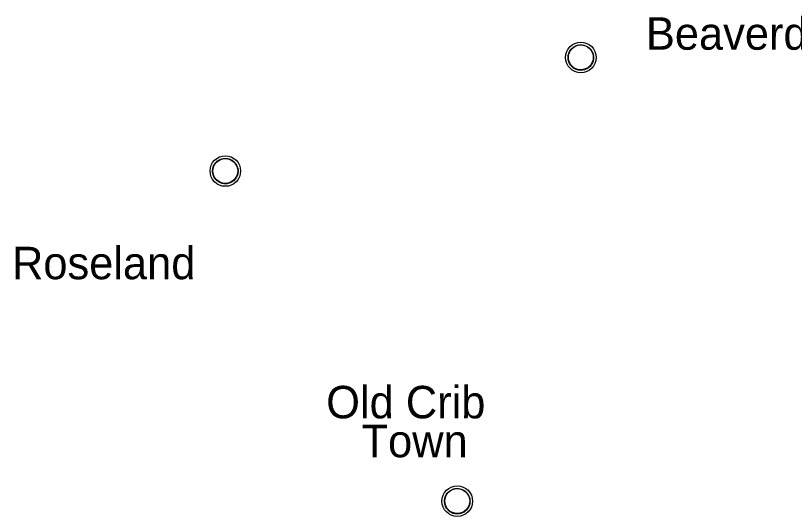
# Model space of a CAD drawing. Extents: x 5197761 to 5514561, y 1890130 to 2080942.
# Drawn here: x 5278705 to 5297901, y 1968768 to 1981120 of the extents above; entities that cross this region are included whole.
import ezdxf

# ---------------------------------------------------------------- set-up
doc = ezdxf.new("R2010")
doc.units = 0
doc.layers.add('Exist Civil Demographics Community CELL', color=7, linetype='Continuous')
doc.layers.add('Exist Civil Demographics Community Label', color=7, linetype='Continuous')

msp = doc.modelspace()

# ---------------------------------------------------------------- linework, layer by layer
at = {"layer": 'Exist Civil Demographics Community CELL'}
for points in [[(5292327, 1980137), (5292331, 1980159), (5292338, 1980185), (5292350, 1980214), (5292361, 1980237), (5292375, 1980260), (5292390, 1980280), (5292406, 1980298), (5292424, 1980316), (5292446, 1980335), (5292468, 1980349), (5292487, 1980361), (5292508, 1980371), (5292529, 1980380), (5292552, 1980387), (5292569, 1980392), (5292589, 1980395), (5292605, 1980398), (5292631, 1980399), (5292648, 1980398), (5292671, 1980397), (5292691, 1980394), (5292710, 1980390), (5292730, 1980385), (5292751, 1980377), (5292777, 1980365), (5292803, 1980351), (5292823, 1980337), (5292843, 1980321), (5292857, 1980308), (5292873, 1980291), (5292889, 1980272), (5292901, 1980254), (5292913, 1980234), (5292923, 1980213), (5292931, 1980193), (5292938, 1980173), (5292943, 1980155), (5292947, 1980130), (5292950, 1980112), (5292951, 1980088), (5292950, 1980064), (5292948, 1980042), (5292944, 1980020), (5292937, 1979995), (5292930, 1979972), (5292921, 1979951), (5292908, 1979927), (5292895, 1979906), (5292881, 1979887), (5292864, 1979868), (5292843, 1979849), (5292823, 1979832), (5292803, 1979818), (5292786, 1979808), (5292758, 1979795), (5292730, 1979785), (5292706, 1979779), (5292680, 1979773), (5292662, 1979772), (5292644, 1979771), (5292622, 1979771), (5292604, 1979772), (5292582, 1979775), (5292558, 1979780), (5292540, 1979786), (5292519, 1979793), (5292501, 1979801), (5292485, 1979810), (5292458, 1979826), (5292436, 1979843), (5292416, 1979861), (5292398, 1979881), (5292385, 1979897), (5292374, 1979913), (5292357, 1979942), (5292350, 1979956), (5292343, 1979972), (5292333, 1980005), (5292327, 1980033), (5292324, 1980054), (5292323, 1980079), (5292323, 1980098), (5292325, 1980123)], [(5283565, 1977336), (5283569, 1977358), (5283576, 1977385), (5283587, 1977414), (5283599, 1977436), (5283612, 1977459), (5283628, 1977480), (5283643, 1977497), (5283662, 1977516), (5283684, 1977534), (5283706, 1977549), (5283725, 1977560), (5283745, 1977570), (5283767, 1977579), (5283790, 1977587), (5283807, 1977591), (5283826, 1977594), (5283843, 1977597), (5283868, 1977598), (5283886, 1977598), (5283909, 1977597), (5283928, 1977594), (5283948, 1977590), (5283968, 1977584), (5283989, 1977576), (5284015, 1977565), (5284040, 1977551), (5284061, 1977536), (5284081, 1977520), (5284095, 1977508), (5284111, 1977490), (5284126, 1977472), (5284139, 1977453), (5284151, 1977433), (5284161, 1977412), (5284169, 1977392), (5284175, 1977372), (5284181, 1977354), (5284185, 1977330), (5284187, 1977311), (5284189, 1977287), (5284188, 1977264), (5284186, 1977241), (5284182, 1977219), (5284175, 1977195), (5284168, 1977171), (5284158, 1977151), (5284146, 1977127), (5284133, 1977106), (5284119, 1977087), (5284102, 1977068), (5284081, 1977048), (5284061, 1977032), (5284041, 1977018), (5284023, 1977008), (5283996, 1976995), (5283968, 1976984), (5283944, 1976978), (5283917, 1976973), (5283900, 1976971), (5283882, 1976970), (5283859, 1976970), (5283842, 1976972), (5283820, 1976975), (5283796, 1976980), (5283778, 1976985), (5283757, 1976993), (5283739, 1977000), (5283723, 1977009), (5283696, 1977026), (5283673, 1977043), (5283654, 1977061), (5283636, 1977080), (5283623, 1977096), (5283611, 1977113), (5283595, 1977141), (5283588, 1977155), (5283581, 1977171), (5283571, 1977204), (5283565, 1977232), (5283562, 1977253), (5283561, 1977278), (5283560, 1977297), (5283563, 1977323)], [(5289281, 1969195), (5289285, 1969217), (5289292, 1969243), (5289304, 1969272), (5289315, 1969295), (5289329, 1969318), (5289344, 1969338), (5289360, 1969356), (5289378, 1969374), (5289400, 1969393), (5289422, 1969407), (5289441, 1969419), (5289462, 1969429), (5289483, 1969438), (5289506, 1969445), (5289523, 1969450), (5289543, 1969453), (5289559, 1969456), (5289585, 1969457), (5289602, 1969456), (5289625, 1969455), (5289645, 1969452), (5289664, 1969448), (5289684, 1969443), (5289705, 1969435), (5289731, 1969423), (5289757, 1969409), (5289777, 1969395), (5289797, 1969379), (5289811, 1969366), (5289827, 1969349), (5289843, 1969330), (5289855, 1969312), (5289867, 1969292), (5289877, 1969271), (5289885, 1969251), (5289892, 1969231), (5289897, 1969213), (5289901, 1969188), (5289904, 1969170), (5289905, 1969146), (5289904, 1969122), (5289902, 1969100), (5289898, 1969078), (5289891, 1969053), (5289884, 1969030), (5289875, 1969010), (5289862, 1968986), (5289849, 1968964), (5289835, 1968945), (5289818, 1968926), (5289797, 1968907), (5289777, 1968890), (5289757, 1968876), (5289740, 1968866), (5289712, 1968853), (5289684, 1968843), (5289660, 1968837), (5289634, 1968832), (5289616, 1968830), (5289598, 1968829), (5289576, 1968829), (5289558, 1968830), (5289536, 1968833), (5289512, 1968838), (5289494, 1968844), (5289473, 1968851), (5289455, 1968859), (5289439, 1968868), (5289412, 1968884), (5289390, 1968901), (5289370, 1968919), (5289352, 1968939), (5289339, 1968955), (5289328, 1968971), (5289311, 1969000), (5289304, 1969014), (5289297, 1969030), (5289287, 1969063), (5289281, 1969091), (5289278, 1969112), (5289277, 1969137), (5289277, 1969156), (5289279, 1969182)]]:
    msp.add_lwpolyline(points, close=True, dxfattribs=at)
for centre, radius in [((5292637, 1980087), 377), ((5292636, 1980088), 307), ((5283875, 1977286), 377), ((5283874, 1977287), 307), ((5289591, 1969145), 377), ((5289590, 1969146), 307)]:
    msp.add_circle(centre, radius, dxfattribs=at)

# ---------------------------------------------------------------- texts
at = {"layer": 'Exist Civil Demographics Community Label'}
for s, p in [('Beaverdam', (5294241, 1980278)), ('Roseland', (5278617, 1974618)), ('Old Crib', (5286361, 1971187)), ('Town', (5287232, 1970227))]:
    msp.add_text(s, height=800, dxfattribs=at).set_placement(p)

doc.saveas('drawing.dxf')
